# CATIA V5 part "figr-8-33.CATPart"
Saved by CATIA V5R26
Part number: Part1
Bounding box of the stored display mesh (mm): x -75 to 75, y -75 to 75, z 0 to 20
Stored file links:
  D:\_Deepak\CATIA\CATIA V5-6R2016_Deepak\Resources\Part files\Partfiles\c08_catia_v5_6r2016_prt\figr-8-33.CATPart
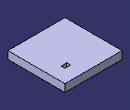
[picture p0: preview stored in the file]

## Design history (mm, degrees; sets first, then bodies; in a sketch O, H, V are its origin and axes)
Body1 (main body)
  Sketch1 on xy-plane, origin (0, 0, 0), H (1, 0, 0), V (0, 1, 0)
    line L1 (-75, 75) -> (75, 75)
    line L2 (75, 75) -> (75, -75)
    line L3 (75, -75) -> (-75, -75)
    line L4 (-75, -75) -> (-75, 75)
    axis line L5 (75, -75) -> (-75, 75)
    length L3 = 150
    length L2 = 150
    horizontal: L1 H, L3 H
    vertical: L2 V, L4 V
    midpoint: O L5
  Pad1: profile Sketch1, direction (0, 0, 1), length 20
  Sketch2 on face of Pad1, origin (0, 0, 20), H (1, 0, 0), V (0, 1, 0)
    line L1 (25, 40) -> (40, 40)
    line L2 (40, 40) -> (40, 30)
    line L3 (40, 30) -> (25, 30)
    line L4 (25, 30) -> (25, 40)
    reference projected line E1 (75, -75) -> (75, 75) from edge [face of Pad1 | face of Pad1]
    reference projected line E2 (75, 75) -> (-75, 75) from edge [face of Pad1 | face of Pad1]
    length L3 = 15
    length L4 = 10
    distance L2 E1 = 35
    distance L1 E2 = 35
    horizontal: L1 H, L3 H
    vertical: L2 V, L4 V
  Pocket1: profile Sketch2, direction (0, 0, -1), through (limit type 3)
